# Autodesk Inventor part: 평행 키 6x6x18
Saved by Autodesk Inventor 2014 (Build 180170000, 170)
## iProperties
Created: 2026-01
Part Number: 평행 키 6x6x18
Material: 일반
Document SubType Name: Modeling
Designer: dg
Density: 1 g/cm^3
Appearance: 기본값
Author: dg
Author: jhkim
Description: 키 및 해당 키홈
Creation Date: 2026-01-09
Sending System: Autodesk Inventor 2026
Preprocessor: ST-DEVELOPER v20.1
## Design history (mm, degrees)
node "평행 키 6x6x181"
body "Solid1"
node "기준1"
